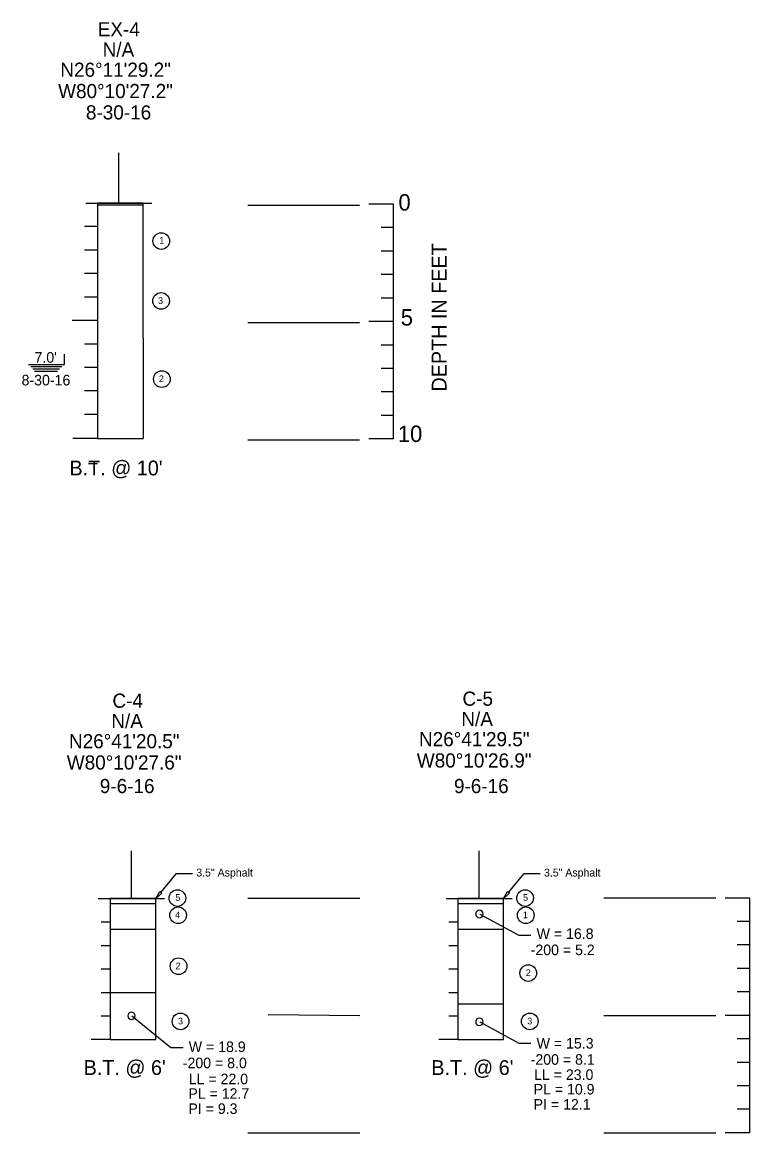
# Model space of a CAD drawing. Extents: x 0 to 331, y -72 to 117.
# Drawn here: x 102.34 to 118.94, y -52.92 to -27.57 of the extents above; entities that cross this region are included whole.
import ezdxf

# ---------------------------------------------------------------- set-up
doc = ezdxf.new("R2010")
doc.units = 0
for name, color, linetype in [('1-BORE', 7, 'Continuous'), ('1-GRID', 7, 'Continuous'), ('1-TEXT', 7, 'Continuous')]:
    doc.layers.add(name, color=color, linetype=linetype)

msp = doc.modelspace()

# ---------------------------------------------------------------- linework, layer by layer
at = {"layer": '1-BORE'}
for p, q in [((104.057, -31.738), (105.102, -31.738)), ((104.057, -34.778), (104.056, -37.067)), ((105.102, -34.778), (105.101, -37.071)), ((104.056, -37.067), (105.101, -37.071)), ((104.342, -47.683), (105.387, -47.683)), ((112.278, -47.683), (113.323, -47.683)), ((112.78, -47.926), (113.672, -48.41)), ((104.342, -48.271), (105.387, -48.271)), ((104.342, -48.271), (105.387, -48.271)), ((112.278, -48.271), (113.323, -48.271)), ((112.278, -48.271), (113.323, -48.271)), ((113.672, -48.41), (113.948, -48.41)), ((104.342, -49.713), (105.387, -49.713)), ((104.342, -49.713), (105.387, -49.713)), ((112.278, -49.971), (113.323, -49.971)), ((112.278, -49.971), (113.323, -49.971)), ((104.84, -50.251), (105.731, -50.971)), ((112.78, -50.389), (113.672, -50.876)), ((104.342, -50.785), (103.913, -50.785)), ((104.342, -50.785), (105.387, -50.785)), ((112.278, -50.785), (111.849, -50.785)), ((112.278, -50.785), (113.323, -50.785)), ((113.672, -50.876), (113.948, -50.875)), ((105.731, -50.971), (106.008, -50.97))]:
    msp.add_line(p, q, dxfattribs=at)
for points in [[(105.102, -34.778), (105.102, -31.697), (104.057, -31.697), (104.057, -34.778)], [(105.102, -31.738), (105.102, -31.697), (104.057, -31.697), (104.057, -31.738), (105.102, -31.738), (105.102, -31.738)], [(105.387, -50.785), (105.387, -47.57), (104.342, -47.57), (104.342, -50.785)], [(105.387, -47.683), (105.387, -47.57), (104.342, -47.57), (104.342, -47.683), (105.387, -47.683), (105.387, -47.683)], [(113.323, -50.785), (113.323, -47.57), (112.278, -47.57), (112.278, -50.785)], [(113.323, -47.683), (113.323, -47.57), (112.278, -47.57), (112.278, -47.683), (113.323, -47.683), (113.323, -47.683)]]:
    msp.add_lwpolyline(points, dxfattribs=at)
for centre, start, end in [((112.773, -47.924), 0, 180), ((112.773, -47.924), 180, 0), ((104.833, -50.25), 0, 180), ((104.833, -50.25), 180, 0), ((112.773, -50.387), 0, 180), ((112.773, -50.387), 180, 0)]:
    msp.add_arc(centre, 0.0848, start, end, dxfattribs=at)
at = {"layer": '1-GRID'}
for p, q in [((107.485, -31.74), (110.039, -31.74)), ((110.815, -31.72), (110.25, -31.72)), ((110.815, -31.72), (110.25, -31.72)), ((104.044, -32.232), (103.759, -32.232)), ((110.815, -32.256), (110.529, -32.256)), ((104.044, -32.768), (103.759, -32.768)), ((110.815, -32.792), (110.529, -32.792)), ((104.044, -33.304), (103.759, -33.304)), ((110.815, -33.328), (110.529, -33.328)), ((104.044, -33.84), (103.759, -33.84)), ((110.815, -33.864), (110.529, -33.864)), ((104.044, -34.376), (103.48, -34.376)), ((107.485, -34.42), (110.039, -34.42)), ((110.815, -34.4), (110.25, -34.4)), ((110.815, -34.4), (110.25, -34.4)), ((104.044, -34.912), (103.759, -34.912)), ((110.815, -34.936), (110.529, -34.936)), ((104.044, -35.447), (103.759, -35.447)), ((110.815, -35.472), (110.529, -35.472)), ((104.044, -35.983), (103.759, -35.983)), ((110.815, -36.007), (110.529, -36.007)), ((104.044, -36.519), (103.759, -36.519)), ((110.815, -36.543), (110.529, -36.543)), ((104.055, -37.067), (103.49, -37.067)), ((107.485, -37.097), (110.039, -37.097)), ((110.815, -37.079), (110.25, -37.079)), ((103.852, -37.643), (104.057, -37.643)), ((107.49, -47.559), (110.043, -47.559)), ((115.615, -47.558), (118.169, -47.558)), ((118.944, -47.56), (118.379, -47.56)), ((118.944, -47.56), (118.379, -47.56)), ((104.137, -48.106), (104.342, -48.106)), ((112.073, -48.106), (112.278, -48.106)), ((118.944, -48.095), (118.658, -48.095)), ((104.137, -48.641), (104.342, -48.641)), ((112.073, -48.641), (112.278, -48.641)), ((118.944, -48.631), (118.658, -48.631)), ((104.137, -49.177), (104.342, -49.177)), ((112.073, -49.177), (112.278, -49.177)), ((118.944, -49.167), (118.658, -49.167)), ((104.137, -49.713), (104.342, -49.713)), ((112.073, -49.713), (112.278, -49.713)), ((118.944, -49.703), (118.658, -49.703)), ((104.137, -50.249), (104.342, -50.249)), ((107.951, -50.22), (110.043, -50.238)), ((112.073, -50.249), (112.278, -50.249)), ((115.615, -50.238), (118.169, -50.238)), ((118.944, -50.239), (118.379, -50.239)), ((118.944, -50.239), (118.379, -50.239)), ((118.944, -50.775), (118.658, -50.775)), ((118.944, -51.311), (118.658, -51.311)), ((118.944, -51.847), (118.658, -51.847)), ((118.944, -52.382), (118.658, -52.382)), ((107.49, -52.918), (110.043, -52.918)), ((115.615, -52.917), (118.169, -52.917)), ((118.944, -52.918), (118.379, -52.918))]:
    msp.add_line(p, q, dxfattribs=at)
for points in [[(110.815, -34.4), (110.815, -31.72)], [(110.815, -37.079), (110.815, -34.4)], [(118.944, -50.239), (118.944, -47.56)], [(118.944, -52.918), (118.944, -50.239)]]:
    msp.add_lwpolyline(points, dxfattribs=at)
at = {"layer": '1-TEXT'}
for p, q in [((104.536, -30.546), (104.536, -31.697)), ((103.306, -35.378), (103.306, -35.142)), ((102.481, -35.378), (103.306, -35.378)), ((102.535, -35.427), (103.245, -35.427)), ((102.582, -35.476), (103.189, -35.476)), ((102.621, -35.535), (103.145, -35.535)), ((104.821, -46.481), (104.821, -47.56)), ((112.757, -46.481), (112.757, -47.56)), ((105.861, -47.002), (106.221, -47.002)), ((113.797, -47.002), (114.157, -47.002))]:
    msp.add_line(p, q, dxfattribs=at)
for points in [[(103.79, -31.697), (105.299, -31.697)], [(105.502, -47.431), (105.861, -47.002)], [(113.438, -47.431), (113.797, -47.002)], [(104.075, -47.567), (105.584, -47.567)], [(112.011, -47.567), (113.52, -47.567)]]:
    msp.add_lwpolyline(points, dxfattribs=at)
for points in [[(105.525, -47.451), (105.387, -47.57), (105.479, -47.412)], [(113.461, -47.451), (113.323, -47.57), (113.415, -47.412)]]:
    msp.add_lwpolyline(points, close=True, dxfattribs=at)
for centre in [(105.512, -32.561), (105.508, -33.929), (105.525, -35.713), (105.879, -47.559), (113.815, -47.559), (105.896, -47.952), (113.832, -47.952), (105.907, -49.116), (113.888, -49.271), (105.951, -50.376), (113.923, -50.376)]:
    msp.add_circle(centre, 0.19, dxfattribs=at)

# ---------------------------------------------------------------- texts
at = {"layer": '1-GRID'}
for s, height, p in [('0', 0.375, (110.925, -31.865)), ('5', 0.375, (110.978, -34.491)), ('10', 0.3751, (110.911, -37.149))]:
    msp.add_text(s, height=height, dxfattribs=at).set_placement(p)
msp.add_text('DEPTH IN FEET', height=0.3376, rotation=90, dxfattribs=at).set_placement((112.022, -35.997))
at = {"layer": '1-TEXT'}
for s, height, p in [('EX-4', 0.3231, (104.061, -27.889)), ('N/A', 0.3231, (104.174, -28.352)), ('N26%%D11\'29.2"', 0.32313, (103.208, -28.812)), ('W80%%D10\'27.2"', 0.32313, (103.158, -29.299)), ('8-30-16', 0.3231, (103.792, -29.786)), ('1', 0.152, (105.466, -32.623)), ('3', 0.152, (105.439, -33.997)), ("  7.0'", 0.2411, (102.44, -35.339)), ('8-30-16', 0.2411, (102.324, -35.857)), ('2', 0.152, (105.457, -35.781)), ("B.T. @ 10'", 0.3376, (103.416, -37.911)), ('C-5', 0.3231, (112.386, -43.17)), ('C-4', 0.3231, (104.397, -43.216)), ('N/A', 0.3231, (104.372, -43.68)), ('N/A', 0.3231, (112.361, -43.634)), ('N26%%D41\'20.5"', 0.32313, (103.405, -44.14)), ('N26%%D41\'29.5"', 0.32313, (111.394, -44.094)), ('W80%%D10\'27.6"', 0.32313, (103.355, -44.626)), ('W80%%D10\'26.9"', 0.32313, (111.344, -44.58)), ('9-6-16', 0.3231, (104.109, -45.164)), ('9-6-16', 0.3231, (112.192, -45.164)), ('3.5" Asphalt', 0.18, (106.311, -47.068)), ('3.5" Asphalt', 0.18, (114.247, -47.068)), ('5', 0.152, (105.833, -47.622)), ('5', 0.152, (113.769, -47.622)), ('4', 0.152, (105.828, -48.02)), ('1', 0.152, (113.764, -48.02)), ('W = 16.8', 0.2411, (114.079, -48.493)), ('-200 = 5.2', 0.2411, (113.943, -48.863)), ('2', 0.152, (105.839, -49.185)), ('2', 0.152, (113.832, -49.339)), ('3', 0.152, (105.895, -50.444)), ('3', 0.152, (113.866, -50.444)), ('W = 18.9', 0.2411, (106.139, -51.075)), ('W = 15.3', 0.2411, (114.079, -50.996)), ('-200 = 8.0', 0.2411, (106.003, -51.444)), ('-200 = 8.1', 0.2411, (113.943, -51.365)), ("B.T. @ 6'", 0.3376, (103.74, -51.598)), ("B.T. @ 6'", 0.3376, (111.676, -51.598)), ('LL = 22.0', 0.2411, (106.139, -51.81)), ('LL = 23.0', 0.2411, (114.02, -51.712)), ('PL = 12.7', 0.2411, (106.131, -52.143)), ('PL = 10.9', 0.2411, (114.011, -52.044)), ('PI = 12.1', 0.2411, (114.011, -52.39)), ('PI = 9.3', 0.2411, (106.131, -52.488))]:
    msp.add_text(s, height=height, dxfattribs=at).set_placement(p)

doc.saveas('drawing.dxf')
